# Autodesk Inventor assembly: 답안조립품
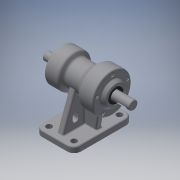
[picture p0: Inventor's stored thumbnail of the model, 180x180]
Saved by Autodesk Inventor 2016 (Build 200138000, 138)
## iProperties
Created: 2015-08
Part Number: 답안조립품
Document SubType Name: Assembly
Designer: Administrator
Author: Administrator
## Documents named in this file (10)
- C:\Users\Administrator\Desktop\450806V1005\답안조립품.iam
- C:\Users\Administrator\Desktop\450806V1005\본체.ipt
- C:\Users\Administrator\Desktop\450806V1005\축.ipt
- C:\Users\Administrator\Desktop\450806V1005\베어링 6205.ipt
- C:\Users\Administrator\Desktop\450806V1005\베어링 6203.ipt
- C:\Users\Administrator\Desktop\450806V1005\앞커버.ipt
- C:\Users\Administrator\Desktop\450806V1005\뒤커버.ipt
- C:\Users\Administrator\Desktop\450806V1005\오일실 .ipt
- 오일실 .ipt
- C:\Users\Administrator\Desktop\450806V1005\M4x0.5.ipt
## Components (10 placed, 1 different names)
1. M4x0.5:1
2. M4x0.5:2
3. M4x0.5:3
4. M4x0.5:4
5. M4x0.5:5
6. M4x0.5:6
7. M4x0.5:7
8. M4x0.5:8
9. M4x0.5:9
10. M4x0.5:10
